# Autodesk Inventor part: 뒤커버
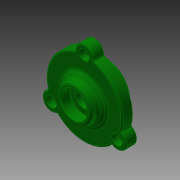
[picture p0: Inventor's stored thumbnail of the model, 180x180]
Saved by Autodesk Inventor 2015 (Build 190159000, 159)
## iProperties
Created: 2016-05
Part Number: 뒤커버
Document SubType Name: Modeling
Designer: mduedu
Density: 2.71 g/cm^3
Material: 알루미늄 6061
Appearance: 진녹색
Author: mduedu
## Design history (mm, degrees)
sketch "스케치1"
  geometry: C1 r 19 at (0, 0); C2 r 29 at (0, 0); 1 further point
  constraints: 2 centre point, 2 coincident
  dimensions: "d33" = 58 diameter of C2; "d34" = 38 diameter of C1
extrude "돌출1" new body sketch "스케치1" distance "d0" = 8; taper "d1" = 0 deg
extrude "돌출2" join sketch "스케치1" distance "d2" = 8; taper "d3" = 0 deg; dims "d35" = 9, "d36" = 0
sketch "스케치5"
  geometry: L1 (-29, 8)-(29, 8) reference; L2 (0, 0)-(0, 15); L3 (-29, 0)-(29, 0) reference; L4 (17.5, 8)-(0, 8); A1 r 25.375 centre (0, -10.375) between (17.5, 8) and (0, 15)
  constraints: 4 end point, 3 point on line, 2 point on circle, 1 centre point, 1 midpoint, 1 perpendicular
  dimensions: "d37" = 17.5 distance from line of L2 L4.start; "d39" = 7 distance from line of L1 L2.end
revolve "회전2" sketch "스케치5" stored, may be unused: angle "d40" = 90 deg
node "작업 평면1"
sketch "스케치6"
  geometry: C1 r 13.5 at (0, 0); 1 further point
  constraints: 1 centre point, 1 coincident
  dimensions: "d42" = 27 diameter of C1
extrude "돌출4" join sketch "스케치6" stored distance "d43" = 10; taper "d44" = 0 deg
sketch "스케치4"
  geometry: L1 (0, -9)-(0, 16); L2 (-15, -9)-(-15, 0); L3 (-15, 0)-(-10, 0); L4 (-10, 0)-(-10, 3); L5 (-10, 3)-(-6, 3); L6 (-6, 3)-(-6, 8.6); L7 (-6, 8.6)-(-10, 8.6); L8 (-10, 8.6)-(-10, 16); L9 (19, -9)-(-19, -9) reference; L10 (-13.5, 16)-(13.5, 16) reference; 1 further point
  constraints: 16 end point, 6 parallel, 3 point on line, 2 midpoint, 1 perpendicular, 1 vertical
  dimensions: "d15" = 30 diameter of L2 L1; "d16" = 20 diameter of L8 L1; "d18" = 9 distance of L2.start L2.end; "d19" = 3 distance of L3.end L4.end; "d20" = 20 diameter of L4 L1; "d21" = 12 diameter of L6 L1; "d45" = 7.4 distance of L7.end L8.end
revolve "회전1" sketch "스케치4" stored, may be unused: angle "d22" = 90 deg
fillet "모깎기2" dims "d23" = 3
fillet "모깎기3" dims "d24" = 0.3
chamfer "모따기2" distance "d46" = 1; stored, may be unused: second distance "d47" = 2, angle "d48" = 45 deg
fillet "모깎기4" dims "d49" = 3
fillet "모깎기5" dims "d50" = 2
sketch "스케치7"
  geometry: C1 r 7 at (0, 29); 2 further points
  constraints: 3 vertical alignment, 1 centre point, 2 other
  dimensions: "d54" = 14 diameter of C1
extrude "돌출5" join sketch "스케치7" stored distance "d55" = 10; taper "d56" = 0 deg
fillet "모깎기6" dims "d57" = 1
fillet "모깎기7" dims "d61" = 1
sketch "스케치8" dims "d62" = 58 (derived)
  geometry: C1 r 18.661 at (0, 0) reference; A1 r 2 centre (-8, 28.914) between (-7.466, 26.986) and (-6, 28.935) reference; A2 r 28 centre (0, 0) between (-7.466, 26.986) and (-27.104, -7.027) reference; A3 r 2 centre (-29.04, -7.529) between (-28.059, -9.272) and (-27.104, -7.027) reference; A4 r 6 centre (-25.115, -14.5) between (-28.059, -9.272) and (-22.059, -19.664) reference; A5 r 2 centre (-21.04, -21.385) between (-19.638, -19.959) and (-22.059, -19.664) reference; A6 r 28 centre (0, 0) between (-19.638, -19.959) and (19.638, -19.959) reference; A7 r 2 centre (21.04, -21.385) between (22.059, -19.664) and (19.638, -19.959) reference; A8 r 6 centre (25.115, -14.5) between (22.059, -19.664) and (28.059, -9.272) reference; A9 r 2 centre (29.04, -7.529) between (27.104, -7.027) and (28.059, -9.272) reference; A10 r 28 centre (0, 0) between (27.104, -7.027) and (7.466, 26.986) reference; A11 r 2 centre (8, 28.914) between (6, 28.935) and (7.466, 26.986) reference; A12 r 6 centre (0, 29) between (6, 28.935) and (-6, 28.935) reference; 4 further points
  constraints: 2 coincident, 1 vertical alignment, 6 other
  dimensions: "d65" = 360 deg dimension on A2.centre point (0, 29) (derived)
sketch "스케치9"
  geometry: A1 r 7 centre (0, 29) between (7, 28.925) and (-7, 28.925) reference; A2 r 7 centre (25.115, -14.5) between (21.55, -20.524) and (28.549, -8.4) reference; A3 r 7 centre (-25.115, -14.5) between (-28.549, -8.4) and (-21.55, -20.524) reference; 3 further points
  constraints: 3 coincident
hole "구멍2" sketch "스케치9" at (-25.115, -14.5), (25.115, -14.5), (0, 29) diameter "d67" = 4.5; stored, may be unused: countersink angle "d71" = 90 deg, drill point angle "d73" = 0 deg; dims "d68" = 6, "d69" = 8, "d70" = 4.6, "d72" = 8
chamfer "모따기3" distance "d76" = 0.7; stored, may be unused: second distance "d77" = 2, angle "d78" = 30 deg
node "솔리드1"
pattern_circular "원형 패턴1" dims angle "d59" = 360 deg
other parameters: "d41" = 8
